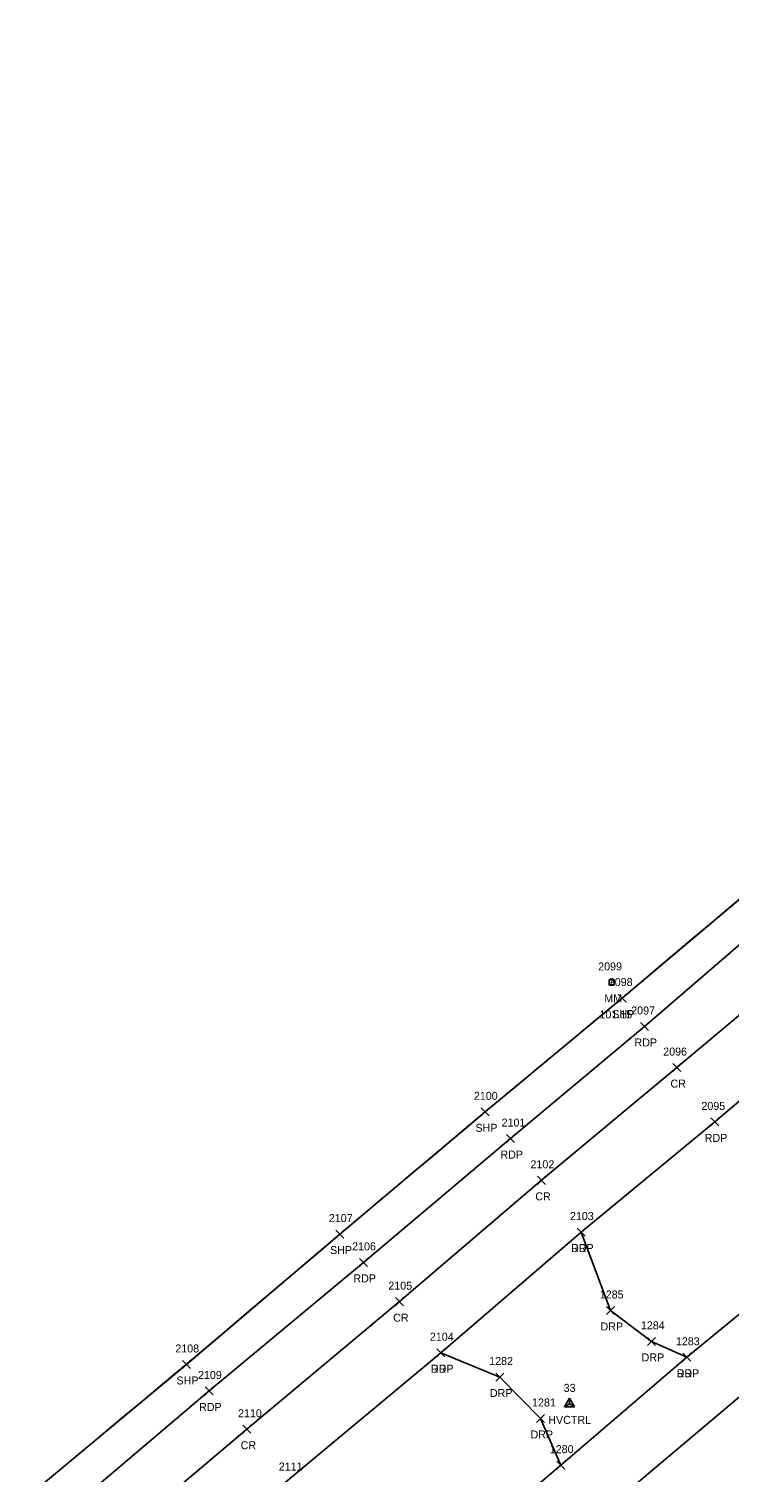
# Model space of a CAD drawing. Extents: x 1472022 to 1479249, y 777216 to 786527.
# Drawn here: x 1472280.1 to 1472455.3, y 777538.1 to 777898.8 of the extents above; entities that cross this region are included whole.
import ezdxf

# ---------------------------------------------------------------- set-up
doc = ezdxf.new("R2010")
doc.units = 0
for name, color, linetype in [('C_A', 7, 'Continuous'), ('C_I', 7, 'Continuous'), ('CPSM', 7, 'Continuous'), ('LSOGP', 7, 'Continuous'), ('P_A', 7, 'Continuous'), ('P_I', 7, 'Continuous'), ('P_TIC', 7, 'Continuous'), ('PET', 7, 'Continuous'), ('PRC', 7, 'Continuous'), ('PSP', 7, 'Continuous'), ('R_A', 7, 'Continuous'), ('R_I', 7, 'Continuous'), ('R_TIC', 7, 'Continuous'), ('RDP', 7, 'Continuous'), ('S_A', 7, 'Continuous'), ('S_C', 7, 'Continuous'), ('S_I', 7, 'Continuous'), ('SRM', 7, 'Continuous')]:
    doc.layers.add(name, color=color, linetype=linetype)

msp = doc.modelspace()

# ---------------------------------------------------------------- linework, layer by layer
at = {"layer": 'CPSM'}
for p, q in [((1472414.08, 777554.46), (1472415.33, 777556.62)), ((1472414.08, 777554.46), (1472415.33, 777555.18)), ((1472416.58, 777554.46), (1472415.33, 777556.62)), ((1472415.33, 777555.18), (1472415.33, 777556.62)), ((1472415.33, 777555.18), (1472415.33, 777555.18)), ((1472415.33, 777555.18), (1472416.58, 777554.46)), ((1472414.08, 777554.46), (1472416.58, 777554.46))]:
    msp.add_line(p, q, dxfattribs=at)
at = {"layer": 'LSOGP'}
msp.add_lwpolyline([(1472459.03, 777682.31), (1472454.67, 777678.64), (1472450.31, 777674.96), (1472445.94, 777671.29), (1472441.58, 777667.61), (1472437.22, 777663.94), (1472432.85, 777660.26), (1472428.49, 777656.59), (1472424.21, 777653.03), (1472419.93, 777649.48), (1472415.66, 777645.93), (1472411.38, 777642.37), (1472407.1, 777638.82), (1472402.82, 777635.27), (1472398.54, 777631.71), (1472394.27, 777628.16), (1472389.72, 777624.34), (1472385.18, 777620.52), (1472380.63, 777616.7), (1472376.09, 777612.88), (1472371.54, 777609.06), (1472367, 777605.25), (1472362.45, 777601.43), (1472357.91, 777597.61), (1472353.1, 777593.54), (1472348.3, 777589.46), (1472343.5, 777585.39), (1472338.7, 777581.32), (1472333.9, 777577.25), (1472329.1, 777573.17), (1472324.3, 777569.1), (1472314.05, 777560.49), (1472308.59, 777555.95), (1472303.14, 777551.41), (1472297.69, 777546.87), (1472292.24, 777542.33), (1472286.79, 777537.79)], dxfattribs=at)
at = {"layer": 'P_TIC'}
for points in [[(1472427.49, 777655.59), (1472429.49, 777657.59)], [(1472429.49, 777655.59), (1472427.49, 777657.59)], [(1472433.09, 777648.49), (1472435.09, 777650.49)], [(1472435.09, 777648.49), (1472433.09, 777650.49)], [(1472441.15, 777638.21), (1472443.15, 777640.21)], [(1472443.15, 777638.21), (1472441.15, 777640.21)], [(1472393.27, 777627.16), (1472395.27, 777629.16)], [(1472395.27, 777627.16), (1472393.27, 777629.16)], [(1472450.66, 777624.63), (1472452.66, 777626.63)], [(1472452.66, 777624.63), (1472450.66, 777626.63)], [(1472399.54, 777620.47), (1472401.54, 777622.47)], [(1472401.54, 777620.47), (1472399.54, 777622.47)], [(1472407.33, 777610.04), (1472409.33, 777612.04)], [(1472409.33, 777610.04), (1472407.33, 777612.04)], [(1472356.91, 777596.61), (1472358.91, 777598.61)], [(1472358.91, 777596.61), (1472356.91, 777598.61)], [(1472417.21, 777597.11), (1472419.21, 777599.11)], [(1472419.21, 777597.11), (1472417.21, 777599.11)], [(1472362.79, 777589.54), (1472364.79, 777591.54)], [(1472364.79, 777589.54), (1472362.79, 777591.54)], [(1472371.78, 777579.72), (1472373.78, 777581.72)], [(1472373.78, 777579.72), (1472371.78, 777581.72)], [(1472318.5, 777564.03), (1472320.5, 777566.03)], [(1472320.5, 777564.03), (1472318.5, 777566.03)], [(1472382.18, 777566.96), (1472384.18, 777568.96)], [(1472384.18, 777566.96), (1472382.18, 777568.96)], [(1472443.63, 777565.82), (1472445.63, 777567.82)], [(1472445.63, 777565.82), (1472443.63, 777567.82)], [(1472324.19, 777557.4), (1472326.19, 777559.4)], [(1472326.19, 777557.4), (1472324.19, 777559.4)], [(1472333.64, 777547.84), (1472335.64, 777549.84)], [(1472335.64, 777547.84), (1472333.64, 777549.84)], [(1472412.17, 777538.86), (1472414.17, 777540.86)], [(1472414.17, 777538.86), (1472412.17, 777540.86)]]:
    msp.add_lwpolyline(points, dxfattribs=at)
at = {"layer": 'PET'}
for points in [[(1472722.68, 777892.48), (1472682.88, 777859.11), (1472639.49, 777823.09), (1472597.79, 777787.8), (1472556.24, 777752.85), (1472511.74, 777714.82), (1472468.29, 777678.86), (1472434.09, 777649.49), (1472400.54, 777621.47), (1472363.79, 777590.54), (1472325.19, 777558.4), (1472281.62, 777521.48), (1472234.5, 777482.07), (1472193.79, 777447.69), (1472152.16, 777412.75), (1472108.18, 777375.84), (1472065.2, 777340.27), (1472030.56, 777311.04)], [(1472700.25, 777835.4), (1472658.9, 777800.89), (1472616.97, 777765.37), (1472574.07, 777728.71), (1472531.82, 777693), (1472487.2, 777655.69), (1472451.66, 777625.63), (1472418.21, 777598.11), (1472383.18, 777567.96), (1472344.18, 777535.52), (1472301.56, 777499.89), (1472253.31, 777459.47), (1472213.07, 777426.05), (1472170.94, 777391.85), (1472126.39, 777354.27), (1472084.25, 777318.79), (1472048.65, 777289.11)], [(1472078.03, 777257.61), (1472120.14, 777293.33), (1472164.04, 777330.1), (1472206.26, 777365.72), (1472247.19, 777400.1), (1472281.71, 777428.77), (1472322.39, 777463.14), (1472366.75, 777500.3), (1472413.17, 777539.86), (1472444.63, 777566.82), (1472482.41, 777597.75), (1472524.08, 777632.67), (1472566.51, 777668.6), (1472612.18, 777706.76), (1472653.17, 777740.78), (1472684.83, 777767.44), (1472722.55, 777799.22)]]:
    msp.add_lwpolyline(points, dxfattribs=at)
at = {"layer": 'PRC'}
for points in [[(1472731.22, 777882.43), (1472690.51, 777848.29), (1472648.7, 777813.67), (1472606.54, 777777.82), (1472564.04, 777742.02), (1472520.37, 777704.66), (1472477.06, 777668.49), (1472442.15, 777639.21), (1472408.33, 777611.04), (1472372.78, 777580.72), (1472334.64, 777548.84), (1472290.86, 777511.89), (1472242.9, 777471.7), (1472202.68, 777437.35), (1472161.87, 777403.07), (1472116.61, 777365.36), (1472074.99, 777330.82), (1472039.59, 777301.03)], [(1472087.18, 777245.54), (1472129.69, 777281.74), (1472174.12, 777318.82), (1472215.99, 777354.07), (1472256.54, 777388.59), (1472291.65, 777417.38), (1472331.92, 777451.29), (1472376.32, 777488.53), (1472423.47, 777528.02), (1472458.4, 777557.41), (1472491.98, 777585.86), (1472533.82, 777621.11), (1472576.2, 777656.67), (1472622.61, 777695.45), (1472662.17, 777728.39), (1472695.49, 777755.92)]]:
    msp.add_lwpolyline(points, dxfattribs=at)
at = {"layer": 'PSP'}
msp.add_lwpolyline([(1472716.04, 777898.78), (1472676.55, 777865.69), (1472632.93, 777829.02), (1472591.62, 777794.25), (1472550.96, 777759.98), (1472505.48, 777721.35), (1472463.4, 777685.99), (1472428.49, 777656.59), (1472394.27, 777628.16), (1472357.91, 777597.61), (1472319.5, 777565.03), (1472275.88, 777528.71), (1472228.56, 777488.93), (1472187.83, 777454.7), (1472146.55, 777420.08), (1472102.55, 777382.93), (1472060.05, 777347.18), (1472024.71, 777317.56)], dxfattribs=at)
at = {"layer": 'R_TIC'}
for points in [[(1472417.21, 777597.11), (1472419.21, 777599.11)], [(1472419.21, 777597.11), (1472417.21, 777599.11)], [(1472424.6, 777577.52), (1472426.6, 777579.52)], [(1472426.6, 777577.52), (1472424.6, 777579.52)], [(1472434.87, 777569.8), (1472436.87, 777571.8)], [(1472436.87, 777569.8), (1472434.87, 777571.8)], [(1472382.18, 777566.96), (1472384.18, 777568.96)], [(1472384.18, 777566.96), (1472382.18, 777568.96)], [(1472443.63, 777565.82), (1472445.63, 777567.82)], [(1472445.63, 777565.82), (1472443.63, 777567.82)], [(1472396.92, 777560.89), (1472398.92, 777562.89)], [(1472398.92, 777560.89), (1472396.92, 777562.89)], [(1472407.09, 777550.53), (1472409.09, 777552.53)], [(1472409.09, 777550.53), (1472407.09, 777552.53)], [(1472412.17, 777538.86), (1472414.17, 777540.86)], [(1472414.17, 777538.86), (1472412.17, 777540.86)]]:
    msp.add_lwpolyline(points, dxfattribs=at)
at = {"layer": 'RDP'}
for points in [[(1472444.63, 777566.82), (1472435.87, 777570.8), (1472425.6, 777578.52), (1472418.21, 777598.11)], [(1472413.17, 777539.86), (1472408.09, 777551.53), (1472397.92, 777561.89), (1472383.18, 777567.96)]]:
    msp.add_lwpolyline(points, dxfattribs=at)
at = {"layer": 'SRM'}
msp.add_lwpolyline([(1472425.22, 777661.13), (1472426.47, 777661.13), (1472426.47, 777659.88), (1472425.22, 777659.88)], close=True, dxfattribs=at)
msp.add_circle((1472425.85, 777660.5), 0.0833, dxfattribs=at)

# ---------------------------------------------------------------- texts
at = {"layer": 'C_A'}
msp.add_text('HVCTRL', height=2, dxfattribs=at).set_placement((1472410.02, 777550.18))
at = {"layer": 'C_I'}
msp.add_text('33', height=2, dxfattribs=at).set_placement((1472413.86, 777558.18))
at = {"layer": 'P_A'}
for s, p in [('SHP', (1472426.02, 777651.59)), ('RDP', (1472431.58, 777644.49)), ('CR', (1472440.58, 777634.21)), ('SHP', (1472391.8, 777623.16)), ('RDP', (1472449.15, 777620.63)), ('RDP', (1472398.03, 777616.47)), ('CR', (1472406.77, 777606.04)), ('SHP', (1472355.44, 777592.61)), ('RDP', (1472415.7, 777593.11)), ('RDP', (1472361.27, 777585.54)), ('CR', (1472371.22, 777575.72)), ('SHP', (1472317.03, 777560.03)), ('RDP', (1472380.66, 777562.96)), ('RDP', (1472442.12, 777561.82)), ('RDP', (1472322.68, 777553.4)), ('CR', (1472333.07, 777543.84))]:
    msp.add_text(s, height=2, dxfattribs=at).set_placement(p)
at = {"layer": 'P_I'}
for s, p in [('2098', (1472425.15, 777659.59)), ('2097', (1472430.76, 777652.49)), ('2096', (1472438.76, 777642.21)), ('2100', (1472391.41, 777631.16)), ('2095', (1472448.32, 777628.63)), ('2101', (1472398.34, 777624.47)), ('2102', (1472405.56, 777614.04)), ('2107', (1472355.13, 777600.61)), ('2103', (1472415.44, 777601.11)), ('2106', (1472360.96, 777593.54)), ('2105', (1472370.01, 777583.72)), ('2104', (1472380.4, 777570.96)), ('2108', (1472316.73, 777568.03)), ('1283', (1472441.94, 777569.82)), ('2109', (1472322.41, 777561.4)), ('2110', (1472332.42, 777551.84)), ('1280', (1472410.39, 777542.86)), ('2111', (1472342.62, 777538.52))]:
    msp.add_text(s, height=2, dxfattribs=at).set_placement(p)
at = {"layer": 'R_A'}
for p in [(1472415.7, 777593.11), (1472423.08, 777573.52), (1472433.36, 777565.8), (1472380.66, 777562.96), (1472442.12, 777561.82), (1472395.41, 777556.89), (1472405.57, 777546.53)]:
    msp.add_text('DRP', height=2, dxfattribs=at).set_placement(p)
at = {"layer": 'R_I'}
for s, p in [('2103', (1472415.44, 777601.11)), ('1285', (1472422.9, 777581.52)), ('2104', (1472380.4, 777570.96)), ('1284', (1472433.18, 777573.8)), ('1283', (1472441.94, 777569.82)), ('1282', (1472395.23, 777564.89)), ('1281', (1472405.96, 777554.53)), ('1280', (1472410.39, 777542.86))]:
    msp.add_text(s, height=2, dxfattribs=at).set_placement(p)
at = {"layer": 'S_A'}
msp.add_text('MM', height=2, dxfattribs=at).set_placement((1472424.04, 777655.5))
at = {"layer": 'S_C'}
msp.add_text('101.15', height=2, dxfattribs=at).set_placement((1472422.82, 777651.5))
at = {"layer": 'S_I'}
msp.add_text('2099', height=2, dxfattribs=at).set_placement((1472422.5, 777663.5))

doc.saveas('drawing.dxf')
